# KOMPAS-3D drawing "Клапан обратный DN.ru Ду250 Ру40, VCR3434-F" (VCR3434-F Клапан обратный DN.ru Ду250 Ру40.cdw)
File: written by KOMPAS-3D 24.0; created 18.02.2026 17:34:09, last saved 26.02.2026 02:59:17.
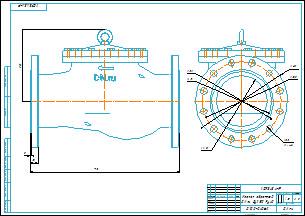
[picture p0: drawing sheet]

Document properties: art: D100-04062; Автор: R2D2; Форматы листов документа: A2; Полное имя файла: VCR3131-F Клапан обратный DN.ru Ду250 Ру40.cdw; Масса: 235; Наименование: Клапан обратный DN.ru Ду250 Ру40; Количество листов документа: 1; Примечание: D100-04062

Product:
- Part/product: Клапан обратный DN.ru Ду250 Ру40  | designation VCR3434-F
    Масса: 235
    Раздел спецификации: Прочие изделия
    Форматы листов документа: A2
    Примечание: D100-04062
    additional columns: D100-04062

Views: Вид 1, Спереди
Referenced files in E:\Работа\Зайцев\VCR3434-F Клапан обратный DN.ru Ду15-300\DN250\: VCR3434-F Клапан обратный DN.ru Ду250 Ру40.m3d
Referenced files in E:\Работа\Зайцев\Для компаса\: чертеж DN.ru А3.cdt
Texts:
  VCR3434-F
  чертеж DN.ru А3.cdt
  Клапан обратный
  DN.ru Ду250 Ру40
  prop
  Клапан обратный DN.ru Ду250 Ру40
  VCR3434-F Клапан обратный DN.ru Ду250 Ру40
Dimensions and other numbers on the sheet: 0; 3; 2; 4; 450; 385; 33; 12 отв.; 250; 292; 312; 1:2,5; 1; 235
